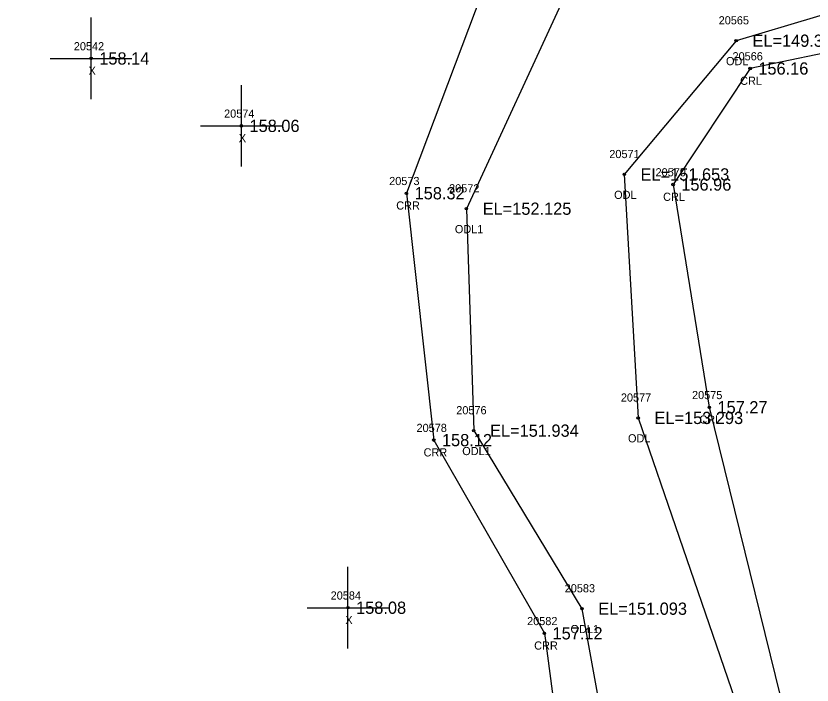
# Model space of a CAD drawing. Extents: x 2279528 to 2280976, y 1061373 to 1062235.
# Drawn here: x 2280219.5 to 2280317.1, y 1061599.1 to 1061681.1 of the extents above; entities that cross this region are included whole.
import ezdxf

# ---------------------------------------------------------------- set-up
doc = ezdxf.new("R2010")
doc.units = 0
for name, color, linetype in [('RD_EX_H2O', 7, 'Continuous'), ('RD_EX_H2O_txCode', 7, 'Continuous'), ('RD_EX_Misc', 7, 'Continuous'), ('RD_EX_Misc_txCode', 7, 'Continuous'), ('RD_EX_TX_H2O_ELEV', 7, 'Continuous'), ('RD_EX_TX_Misc_ELEV', 7, 'Continuous'), ('RD_SMD_Locator', 7, 'Continuous')]:
    doc.layers.add(name, color=color, linetype=linetype)

msp = doc.modelspace()

# ---------------------------------------------------------------- linework, layer by layer
at = {"layer": 'RD_EX_H2O'}
for points in [[(2280243.564, 1061789.126), (2280258.669, 1061797.273), (2280267.662, 1061787.819), (2280287.799, 1061761.364), (2280315.218, 1061731.796), (2280327.476, 1061683.928), (2280307.757, 1061678.038), (2280294.04, 1061661.652), (2280295.741, 1061631.812), (2280310.809, 1061587.935), (2280304.483, 1061546.386), (2280272.845, 1061527.926), (2280259.985, 1061540.364), (2280245.208, 1061537.05), (2280265.992, 1061500.754), (2280299.658, 1061476.278), (2280353.727, 1061471.295), (2280375.17, 1061457.424), (2280376.846, 1061433.194), (2280358.103, 1061419.487), (2280333.324, 1061393.345)], [(2280269.902, 1061794.485), (2280270.025, 1061790.742), (2280293.77, 1061763.475), (2280320.491, 1061735.048), (2280335.4, 1061680.015), (2280309.476, 1061674.63), (2280300.031, 1061660.413), (2280304.467, 1061633.116), (2280315.65, 1061587.638), (2280305.886, 1061543.574), (2280270.769, 1061524.544), (2280257.608, 1061536.276), (2280249.22, 1061535.261), (2280269.329, 1061502.829), (2280301.338, 1061480.019), (2280355.942, 1061475.367), (2280377.908, 1061459.941), (2280379.033, 1061432.998), (2280360.127, 1061417.181), (2280333.785, 1061387.953)], [(2280219.486, 1061771.902), (2280219.452, 1061768.678), (2280220.023, 1061767.068), (2280223.007, 1061764.942), (2280232.418, 1061752.335), (2280266.067, 1061747.742), (2280284.728, 1061725.481), (2280294.864, 1061698.386), (2280278.352, 1061688.538), (2280267.334, 1061659.345), (2280270.687, 1061629.09), (2280284.247, 1061605.417), (2280287.803, 1061578.535), (2280274.538, 1061562.246), (2280261.241, 1061561.709), (2280231.845, 1061561.455), (2280221.241, 1061537.208), (2280230.805, 1061514.202), (2280261.741, 1061476.456), (2280301.474, 1061455.379), (2280325.747, 1061454.259), (2280345.438, 1061445.285), (2280345.675, 1061436.485), (2280313.46, 1061411.549)], [(2280269.444, 1061752.221), (2280294.623, 1061728.954), (2280307.916, 1061693.905), (2280286.99, 1061684.109), (2280274.679, 1061657.451), (2280275.583, 1061630.253), (2280288.855, 1061608.435), (2280293.716, 1061581.702), (2280282.363, 1061552.424), (2280261.544, 1061554.567), (2280239.334, 1061554.649), (2280226.999, 1061538.36), (2280233.842, 1061514.574), (2280265.755, 1061478.909), (2280302.981, 1061460.154), (2280326.028, 1061460.105), (2280352.944, 1061451.166), (2280354.087, 1061431.943), (2280317.153, 1061398.724)]]:
    msp.add_lwpolyline(points, dxfattribs=at)
at = {"layer": 'RD_EX_Misc'}
for p, q in [((2280228.671, 1061670.861), (2280228.671, 1061680.861)), ((2280223.671, 1061675.861), (2280233.671, 1061675.861)), ((2280247.093, 1061662.603), (2280247.093, 1061672.603)), ((2280242.093, 1061667.603), (2280252.093, 1061667.603)), ((2280260.158, 1061603.551), (2280260.158, 1061613.551)), ((2280255.158, 1061608.551), (2280265.158, 1061608.551))]:
    msp.add_line(p, q, dxfattribs=at)
at = {"layer": 'RD_SMD_Locator'}
for centre in [(2280307.757, 1061678.038), (2280228.671, 1061675.861), (2280309.476, 1061674.63), (2280247.093, 1061667.603), (2280294.04, 1061661.652), (2280300.031, 1061660.413), (2280267.334, 1061659.345), (2280274.679, 1061657.451), (2280304.467, 1061633.116), (2280295.741, 1061631.812), (2280275.583, 1061630.253), (2280270.687, 1061629.09), (2280260.158, 1061608.551), (2280288.855, 1061608.435), (2280284.247, 1061605.417)]:
    msp.add_circle(centre, 0.15, dxfattribs=at)

# ---------------------------------------------------------------- texts
at = {"layer": 'RD_EX_H2O_txCode'}
for s, p in [('20565', (2280305.615, 1061680.038)), ('20566', (2280307.31, 1061675.63)), ('ODL', (2280306.513, 1061675.038)), ('CRL', (2280308.247, 1061672.63)), ('20571', (2280292.205, 1061663.652)), ('20570', (2280297.874, 1061661.413)), ('20573', (2280265.216, 1061660.345)), ('20572', (2280272.561, 1061659.451)), ('ODL', (2280292.796, 1061658.652)), ('CRL', (2280298.803, 1061658.413)), ('CRR', (2280266.082, 1061657.345)), ('ODL1', (2280273.269, 1061654.451)), ('20577', (2280293.623, 1061633.812)), ('20575', (2280302.349, 1061634.116)), ('20576', (2280273.441, 1061632.253)), ('CRL', (2280303.239, 1061631.116)), ('20578', (2280268.569, 1061630.09)), ('ODL', (2280294.497, 1061628.812)), ('CRR', (2280269.435, 1061627.09)), ('ODL1', (2280274.173, 1061627.253)), ('20583', (2280286.737, 1061610.435)), ('20582', (2280282.129, 1061606.417)), ('ODL1', (2280287.446, 1061605.435)), ('CRR', (2280282.995, 1061603.417))]:
    msp.add_text(s, height=1, dxfattribs=at).set_placement(p)
at = {"layer": 'RD_EX_Misc_txCode'}
for s, p in [('20542', (2280226.552, 1061676.861)), ('X', (2280228.356, 1061673.861)), ('20574', (2280244.975, 1061668.603)), ('X', (2280246.778, 1061665.603)), ('20584', (2280258.04, 1061609.551)), ('X', (2280259.843, 1061606.551))]:
    msp.add_text(s, height=1, dxfattribs=at).set_placement(p)
at = {"layer": 'RD_EX_TX_H2O_ELEV'}
for s, p in [('EL=149.334', (2280309.757, 1061677.288)), ('156.16', (2280310.476, 1061673.88)), ('EL=151.653', (2280296.04, 1061660.902)), ('156.96', (2280301.031, 1061659.663)), ('158.32', (2280268.334, 1061658.595)), ('EL=152.125', (2280276.679, 1061656.701)), ('157.27', (2280305.467, 1061632.366)), ('EL=153.293', (2280297.741, 1061631.062)), ('EL=151.934', (2280277.583, 1061629.503)), ('158.12', (2280271.687, 1061628.34)), ('EL=151.093', (2280290.855, 1061607.685)), ('157.12', (2280285.247, 1061604.667))]:
    msp.add_text(s, height=1.5, dxfattribs=at).set_placement(p)
at = {"layer": 'RD_EX_TX_Misc_ELEV'}
for s, p in [('158.14', (2280229.671, 1061675.111)), ('158.06', (2280248.093, 1061666.853)), ('158.08', (2280261.158, 1061607.801))]:
    msp.add_text(s, height=1.5, dxfattribs=at).set_placement(p)

doc.saveas('drawing.dxf')
